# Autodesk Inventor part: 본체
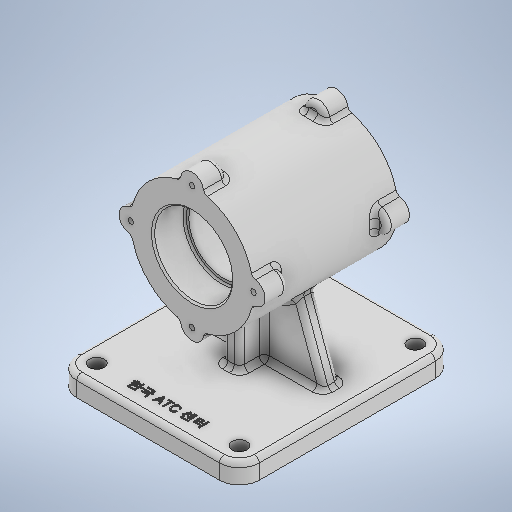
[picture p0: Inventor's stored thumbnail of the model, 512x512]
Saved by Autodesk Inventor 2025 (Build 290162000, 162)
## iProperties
Created: 2024-08
Part Number: 본체
Material: 일반
Document SubType Name: Modeling
Designer: deana
Density: 1 g/cm^3
Appearance: 기본값
Mass: 435.956 g
Surface Area: 772.832 cm^2
Volume: 435.956 cm^3
Author: deana
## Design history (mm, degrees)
sketch "스케치1"
  geometry: L1 (43, -60)-(-43, -60); L2 (-55, -48)-(-55, 58); L3 (-43, 70)-(43, 70); L4 (55, 58)-(55, -48); L5 (55, -60)-(-55, 70); L6 (-55, -60)-(55, 70); A1 r 12 centre (43, -48) between (43, -60) and (55, -48); A2 r 12 centre (-43, -48) between (-55, -48) and (-43, -60); A3 r 12 centre (-43, 58) between (-43, 70) and (-55, 58); A4 r 12 centre (43, 58) between (55, 58) and (43, 70); 2 further points
  constraints: 12 end point, 8 point on circle, 8 point on line, 8 tangent, 4 centre point, 3 equal radius, 2 midpoint, 2 parallel, 1 horizontal, 1 perpendicular, 1 vertical alignment
  dimensions: "d0" = 110 distance of L5.end L6.end; "d1" = 130 distance of L6.start L5.end; "d2" = 12 radius of A1; "d42" = 5 distance of point (0, 0) point (0, 5); "d43" = 70 distance from line of L3 point (0, 0) (derived)
extrude "돌출1" new body sketch "스케치1" distance "d3" = 12; taper "d4" = 0 deg
sketch "스케치2"
  geometry: C1 r 37 at (0, 82); 1 further point
  constraints: 1 centre point, 1 vertical alignment
  dimensions: "d5" = 74 diameter of C1; "d6" = 82 distance of point (0, 0) C1.centre
extrude "돌출2" join sketch "스케치2" stored distance "d7" = 87; taper "d8" = 0 deg
sketch "스케치3"
  geometry: C1 r 7 at (0, 37); 2 further points
  constraints: 2 vertical alignment, 1 centre point, 1 other
  dimensions: "d9" = 14 diameter of C1
extrude "돌출3" join sketch "스케치3" distance "d10" = 14; taper "d11" = 0 deg
sketch "스케치4"
  geometry: A1 r 7 centre (0, 119) between (6.969, 118.338) and (-6.969, 118.338) reference; 2 further points
  constraints: 1 coincident
hole "구멍1" sketch "스케치4" at (0, 119) diameter "d12" = 3.242; stored, may be unused: countersink angle "d16" = 90 deg, drill point angle "d18" = 120 deg; dims "d13" = 8, "d14" = 4, "d15" = 2, "d17" = 10
fillet "모깎기1" dims "d19" = 3
fillet "모깎기2" dims "d20" = 3
sketch "스케치5"
  geometry: L1 (0, 119.152)-(0, 12); L2 (0, 12)-(41, 12); L3 (41, 12)-(13.124, 88.587); L4 (43, 12)-(-43, 12) reference; L5 (55, 12)-(43, 12) reference; L6 (-41, 12)-(-13.124, 88.587); L7 (0, 12)-(-41, 12); L8 (-43, 0)-(43, 0) reference; L9 (55, 0)-(55, 12) reference; L10 (-13.124, 88.587)-(13.124, 88.587); L11 (-55, 0)-(-55, 12) reference; L12 (-43, 12)-(-55, 12) reference; 6 further points
  constraints: 12 end point, 1 horizontal, 1 horizontal alignment, 1 midpoint, 1 perpendicular, 1 symmetric about line, 1 vertical, 1 vertical alignment
  dimensions: "d25" = 110 deg angle of L5 L3; "d26" = 14 distance of L5.start L2.end; "d29" = 26.24893 distance of L3.end L6.end; "d86" = 110 deg angle of L12 L6; "d87" = 14 distance of L11.end L6.start (derived)
extrude "돌출4" join sketch "스케치5" stored distance "d27" = 10; taper "d28" = 0 deg
sketch "스케치7"
  geometry: L1 (4.473, 20)-(81.429, 20); L2 (81.429, 20)-(81.429, -20); L3 (81.429, -20)-(4.473, -20); L4 (4.473, -20)-(4.473, 20); L5 (4.473, 20)-(81.429, -20); L6 (81.429, 20)-(4.473, -20); L7 (0, 70)-(12, 70) reference; 4 further points
  constraints: 12 end point, 4 midpoint, 2 parallel, 1 horizontal, 1 perpendicular
  dimensions: "d36" = 40 distance of L2.end L1.end; "d37" = 50 vertical distance of point (6, 70) point (42.951, 20); "d38" = 76.95648 distance of L2.end L3.end; "d39" = 4.47297 horizontal distance of point (0, 0) L3.end
extrude "돌출6" join sketch "스케치7" stored distance "d44" = 10; taper "d45" = 0 deg
fillet "모깎기3" dims "d46" = 3
fillet "모깎기4" dims "d47" = 3
fillet "모깎기5" dims "d48" = 3
fillet "모깎기6" dims "d56" = 3
sketch "스케치9"
  geometry: L1 (-43, -70)-(43, -70) reference; 2 further points
  constraints: 1 vertical alignment, 1 other
  dimensions: "d58" = 58 distance of point (0, 0) point (0, -58)
feature "엠보싱1" sketch "스케치9" dims "d61" = 0.5, "d62" = 0
sketch "스케치10"
  geometry: L1 (82, 43.5)-(105.5, 43.5); L2 (105.5, 43.5)-(105.5, 25.5); L3 (104.5, 24.5)-(103, 24.5); L4 (103, 24.5)-(103, 0); L5 (103, 0)-(105.879, 0); L6 (103, -24.5)-(103, 0); L7 (104.5, -24.5)-(103, -24.5); L8 (105.5, -43.5)-(105.5, -25.5); L9 (82, -43.5)-(105.5, -43.5); L10 (82, 43.5)-(82, -43.5); L11 (82, 43.5)-(82, 56.947); L12 (0, 70)-(9, 70) reference; A1 r 1 centre (104.5, 25.5) between (104.5, 24.5) and (105.5, 25.5); A2 r 1 centre (104.5, -25.5) between (105.5, -25.5) and (104.5, -24.5); 4 further points
  constraints: 22 end point, 4 point on circle, 4 point on line, 4 symmetric about line, 4 tangent, 3 perpendicular, 2 centre point, 2 horizontal, 2 vertical, 1 equal radius, 1 midpoint
  dimensions: "d63" = 87 distance of L8.start L1.end; "d64" = 19 distance of L1.end point (105.5, 24.5); "d65" = 47 diameter of L1.end L11; "d66" = 42 diameter of L3.end L11; "d67" = 1 radius of A1; "d68" = 70 vertical distance of L12.end point (82, 0); "d69" = 82 distance of point (0, 0) point (82, 0)
revolve "회전1" sketch "스케치10" stored, may be unused: angle "d70" = 90 deg
chamfer "모따기1" distance "d71" = 1; stored, may be unused: second distance "d72" = 2, angle "d73" = 45 deg
sketch "스케치11"
  geometry: L1 (-43, 48)-(43, 48); L2 (43, 48)-(43, -58); L3 (43, -58)-(-43, -58); L4 (-43, -58)-(-43, 48); L5 (-43, 48)-(43, -58); L6 (43, 48)-(-43, -58); L7 (-43, -70)-(43, -70) reference; 2 further points
  constraints: 12 end point, 2 midpoint, 2 parallel, 1 horizontal, 1 perpendicular, 1 vertical alignment
  dimensions: "d75" = 86 distance of L2.end L3.end; "d76" = 106 distance of L1.end L2.end; "d77" = 12 distance from line of L7 L2.end
hole "구멍3" sketch "스케치11" at (-43, -58), (43, -58), (43, 48), (-43, 48) diameter "d78" = 9; stored, may be unused: countersink angle "d82" = 90 deg, drill point angle "d84" = 0 deg; dims "d79" = 6, "d80" = 4, "d81" = 2, "d83" = 15
node "솔리드1"
pattern_circular "원형 패턴1" dims "d22" = 360 deg
mirror "미러1"
feature "A9D066F2-1C7D-4E18-AEED-F7BC21143FA4" dims "d78" = 9, "d79" = 6, "d80" = 4, "d81" = 2, "d82" = 90 deg, "d83" = 15, "d84" = 0
